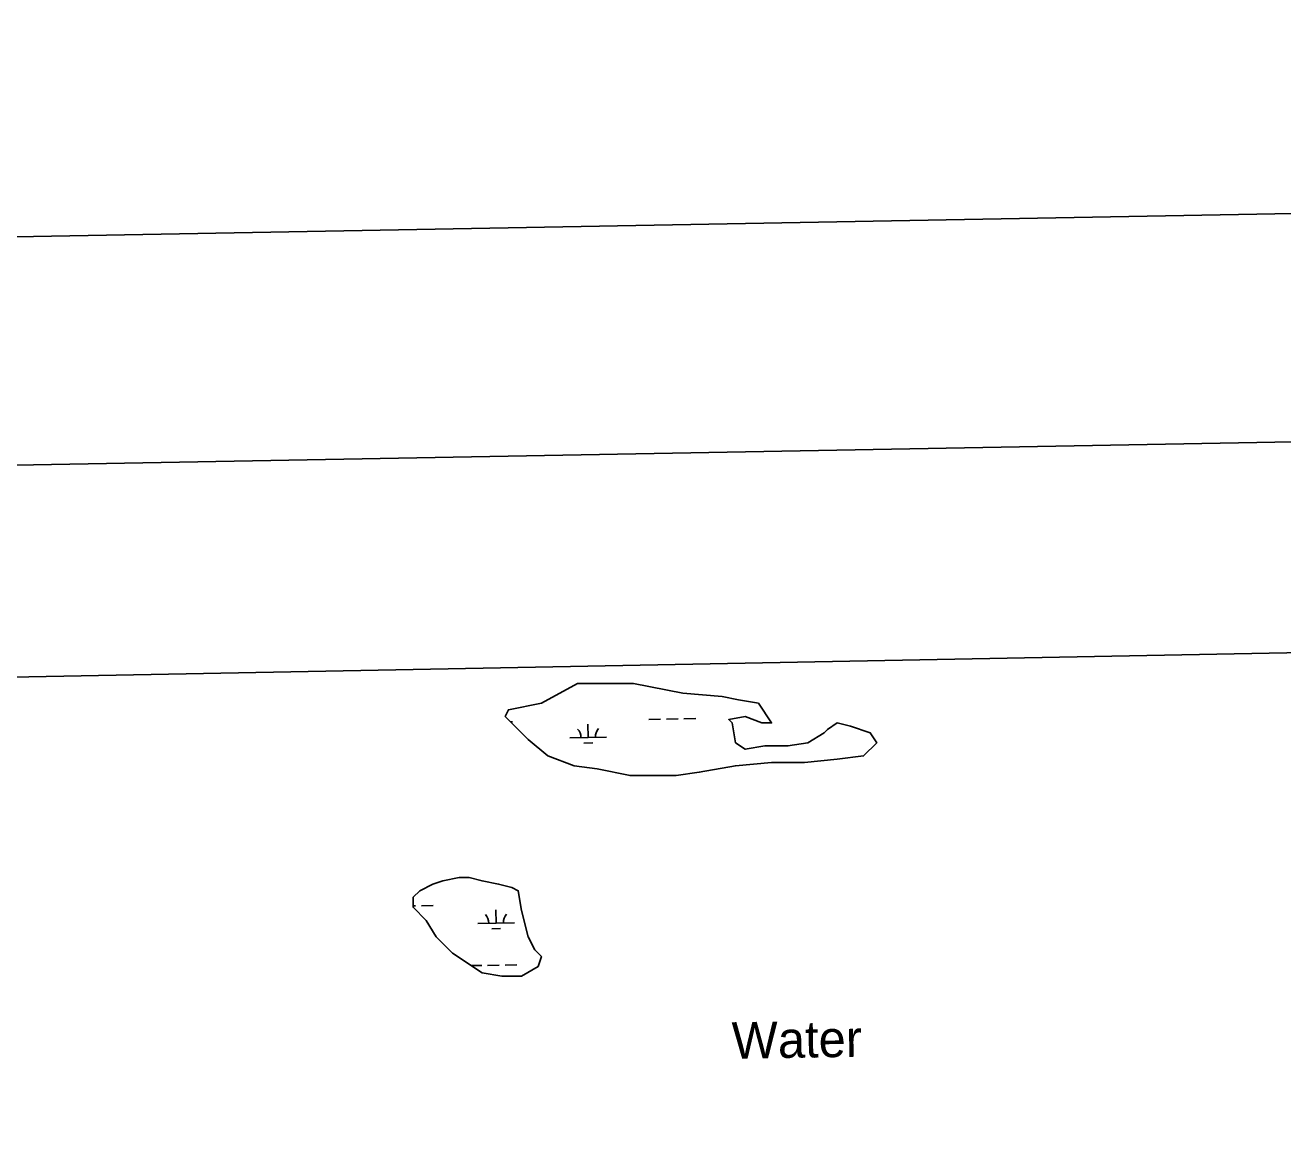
# Model space of a CAD drawing. Extents: x 3957609 to 3995875, y 234277 to 260273.
# Drawn here: x 3963008 to 3966451, y 256682 to 259690 of the extents above; entities that cross this region are included whole.
import ezdxf

# ---------------------------------------------------------------- set-up
doc = ezdxf.new("R2010")
doc.units = 0
for name, color, linetype in [('G-ANNO-NPLT', 7, 'Continuous'), ('V-ANNO-SYMB', 7, 'Continuous'), ('V-GRID-FRAM', 7, 'Continuous'), ('V-RIVR-IDEN', 7, 'Continuous'), ('V-TOPO-SHOR', 7, 'Continuous'), ('V-WETL-SWMP', 7, 'Continuous')]:
    doc.layers.add(name, color=color, linetype=linetype)

msp = doc.modelspace()

# ---------------------------------------------------------------- linework, layer by layer
at = {"layer": 'G-ANNO-NPLT'}
msp.add_lwpolyline([(3958631.604, 234860.578), (3995292.211, 235527.18), (3994852.859, 259689.853), (3958192.252, 259023.251)], close=True, dxfattribs=at)
at = {"layer": 'V-ANNO-SYMB'}
msp.add_lwpolyline([(3961369.919, 235535.518), (3994447.652, 236136.973), (3994031.027, 259049.761), (3960953.294, 258448.306), (3961369.919, 235535.518)], dxfattribs=at)
at = {"layer": 'V-GRID-FRAM'}
for points in [[(3961534.646, 257877.621), (3993438.57, 258485.581), (3993792.928, 240306.336), (3961873.139, 239698.074), (3961534.646, 257877.621)], [(3961534.646, 257877.621), (3993438.57, 258485.581)]]:
    msp.add_lwpolyline(points, dxfattribs=at)
at = {"layer": 'V-TOPO-SHOR'}
for points in [[(3964808.488, 257860.45), (3964916.517, 257851.442), (3964961.528, 257842.433), (3965015.543, 257833.425), (3965051.552, 257779.374), (3965024.545, 257779.374), (3964979.533, 257797.391), (3964934.521, 257788.382), (3964943.524, 257779.374), (3964952.526, 257725.323), (3964979.533, 257707.306), (3965033.547, 257716.315), (3965096.564, 257716.315), (3965150.578, 257725.323), (3965195.59, 257752.349), (3965204.592, 257761.357), (3965231.599, 257779.374), (3965267.608, 257770.366), (3965321.623, 257752.349), (3965339.627, 257725.323), (3965303.618, 257689.289), (3965231.599, 257680.281), (3965141.575, 257671.273), (3965051.552, 257671.273), (3964952.526, 257662.264), (3964853.5, 257644.247), (3964790.484, 257635.239), (3964664.451, 257635.239), (3964574.427, 257653.256), (3964511.411, 257662.264), (3964439.392, 257689.289), (3964385.378, 257734.332), (3964322.361, 257797.391), (3964331.364, 257815.408), (3964421.387, 257833.425), (3964520.413, 257887.475), (3964673.453, 257887.475)], [(3964367.373, 257265.892), (3964385.378, 257193.825), (3964403.383, 257157.791), (3964421.387, 257139.774), (3964412.385, 257112.748), (3964367.373, 257085.723), (3964313.359, 257085.723), (3964259.345, 257094.732), (3964178.324, 257148.782), (3964133.312, 257193.825), (3964106.305, 257238.867), (3964070.296, 257274.901), (3964070.296, 257301.926), (3964088.3, 257319.943), (3964124.31, 257337.96), (3964151.317, 257346.968), (3964196.328, 257355.977), (3964223.336, 257355.977), (3964259.345, 257346.968), (3964304.357, 257337.96), (3964340.366, 257328.951), (3964358.371, 257319.943)]]:
    msp.add_lwpolyline(points, close=True, dxfattribs=at)
at = {"layer": 'V-WETL-SWMP'}
for p, q in [((3964715.878, 257789.175), (3964747.873, 257789.756)), ((3964715.878, 257789.175), (3964747.873, 257789.756)), ((3964715.878, 257789.175), (3964747.873, 257789.756)), ((3964763.87, 257790.047), (3964795.865, 257790.629)), ((3964763.87, 257790.047), (3964795.865, 257790.629)), ((3964763.87, 257790.047), (3964795.865, 257790.629)), ((3964811.862, 257790.92), (3964843.857, 257791.502)), ((3964811.862, 257790.92), (3964843.857, 257791.502)), ((3964811.862, 257790.92), (3964843.857, 257791.502)), ((3964337.448, 257782.294), (3964342.032, 257782.377)), ((3964337.448, 257782.294), (3964342.032, 257782.377)), ((3964337.448, 257782.294), (3964342.032, 257782.377)), ((3964549.686, 257739.715), (3964549.031, 257775.709)), ((3964549.686, 257739.715), (3964549.031, 257775.709)), ((3964549.686, 257739.715), (3964549.031, 257775.709)), ((3965050.956, 257779.374), (3965050.939, 257780.294)), ((3965050.956, 257779.374), (3965050.939, 257780.294)), ((3965050.956, 257779.374), (3965050.939, 257780.294)), ((3964499.694, 257738.806), (3964599.677, 257740.624)), ((3964499.694, 257738.806), (3964599.677, 257740.624)), ((3964499.694, 257738.806), (3964599.677, 257740.624)), ((3964537.968, 257724.068), (3964561.964, 257724.505)), ((3964537.968, 257724.068), (3964561.964, 257724.505)), ((3964537.968, 257724.068), (3964561.964, 257724.505)), ((3964070.296, 257278.177), (3964077.244, 257278.304)), ((3964070.296, 257278.177), (3964077.244, 257278.304)), ((3964070.296, 257278.177), (3964077.244, 257278.304)), ((3964093.241, 257278.595), (3964125.236, 257279.176)), ((3964093.241, 257278.595), (3964125.236, 257279.176)), ((3964093.241, 257278.595), (3964125.236, 257279.176)), ((3964297.446, 257231.557), (3964296.792, 257267.551)), ((3964297.446, 257231.557), (3964296.792, 257267.551)), ((3964297.446, 257231.557), (3964296.792, 257267.551)), ((3964247.455, 257230.648), (3964347.438, 257232.466)), ((3964247.455, 257230.648), (3964347.438, 257232.466)), ((3964247.455, 257230.648), (3964347.438, 257232.466)), ((3964285.729, 257215.911), (3964309.725, 257216.347)), ((3964285.729, 257215.911), (3964309.725, 257216.347)), ((3964285.729, 257215.911), (3964309.725, 257216.347)), ((3964229.166, 257114.865), (3964258.144, 257115.392)), ((3964229.166, 257114.865), (3964258.144, 257115.392)), ((3964229.166, 257114.865), (3964258.144, 257115.392)), ((3964274.141, 257115.683), (3964306.136, 257116.264)), ((3964274.141, 257115.683), (3964306.136, 257116.264)), ((3964274.141, 257115.683), (3964306.136, 257116.264)), ((3964322.133, 257116.555), (3964354.128, 257117.137)), ((3964322.133, 257116.555), (3964354.128, 257117.137)), ((3964322.133, 257116.555), (3964354.128, 257117.137))]:
    msp.add_line(p, q, dxfattribs=at)
for points in [[(3964808.488, 257860.45), (3964916.517, 257851.442), (3964961.528, 257842.433), (3965015.543, 257833.425), (3965051.552, 257779.374), (3965024.545, 257779.374), (3964979.533, 257797.391), (3964934.521, 257788.382), (3964943.524, 257779.374), (3964952.526, 257725.323), (3964979.533, 257707.306), (3965033.547, 257716.315), (3965096.564, 257716.315), (3965150.578, 257725.323), (3965195.59, 257752.349), (3965204.592, 257761.357), (3965231.599, 257779.374), (3965267.608, 257770.366), (3965321.623, 257752.349), (3965339.627, 257725.323), (3965303.618, 257689.289), (3965231.599, 257680.281), (3965141.575, 257671.273), (3965051.552, 257671.273), (3964952.526, 257662.264), (3964853.5, 257644.247), (3964790.484, 257635.239), (3964664.451, 257635.239), (3964574.427, 257653.256), (3964511.411, 257662.264), (3964439.392, 257689.289), (3964385.378, 257734.332), (3964322.361, 257797.391), (3964331.364, 257815.408), (3964421.387, 257833.425), (3964520.413, 257887.475), (3964673.453, 257887.475)], [(3964808.488, 257860.45), (3964916.517, 257851.442), (3964961.528, 257842.433), (3965015.543, 257833.425), (3965051.552, 257779.374), (3965024.545, 257779.374), (3964979.533, 257797.391), (3964934.521, 257788.382), (3964943.524, 257779.374), (3964952.526, 257725.323), (3964979.533, 257707.306), (3965033.547, 257716.315), (3965096.564, 257716.315), (3965150.578, 257725.323), (3965195.59, 257752.349), (3965204.592, 257761.357), (3965231.599, 257779.374), (3965267.608, 257770.366), (3965321.623, 257752.349), (3965339.627, 257725.323), (3965303.618, 257689.289), (3965231.599, 257680.281), (3965141.575, 257671.273), (3965051.552, 257671.273), (3964952.526, 257662.264), (3964853.5, 257644.247), (3964790.484, 257635.239), (3964664.451, 257635.239), (3964574.427, 257653.256), (3964511.411, 257662.264), (3964439.392, 257689.289), (3964385.378, 257734.332), (3964322.361, 257797.391), (3964331.364, 257815.408), (3964421.387, 257833.425), (3964520.413, 257887.475), (3964673.453, 257887.475)], [(3964808.488, 257860.45), (3964916.517, 257851.442), (3964961.528, 257842.433), (3965015.543, 257833.425), (3965051.552, 257779.374), (3965024.545, 257779.374), (3964979.533, 257797.391), (3964934.521, 257788.382), (3964943.524, 257779.374), (3964952.526, 257725.323), (3964979.533, 257707.306), (3965033.547, 257716.315), (3965096.564, 257716.315), (3965150.578, 257725.323), (3965195.59, 257752.349), (3965204.592, 257761.357), (3965231.599, 257779.374), (3965267.608, 257770.366), (3965321.623, 257752.349), (3965339.627, 257725.323), (3965303.618, 257689.289), (3965231.599, 257680.281), (3965141.575, 257671.273), (3965051.552, 257671.273), (3964952.526, 257662.264), (3964853.5, 257644.247), (3964790.484, 257635.239), (3964664.451, 257635.239), (3964574.427, 257653.256), (3964511.411, 257662.264), (3964439.392, 257689.289), (3964385.378, 257734.332), (3964322.361, 257797.391), (3964331.364, 257815.408), (3964421.387, 257833.425), (3964520.413, 257887.475), (3964673.453, 257887.475)], [(3964367.373, 257265.892), (3964385.378, 257193.825), (3964403.383, 257157.791), (3964421.387, 257139.774), (3964412.385, 257112.748), (3964367.373, 257085.723), (3964313.359, 257085.723), (3964259.345, 257094.732), (3964178.324, 257148.782), (3964133.312, 257193.825), (3964106.305, 257238.867), (3964070.296, 257274.901), (3964070.296, 257301.926), (3964088.3, 257319.943), (3964124.31, 257337.96), (3964151.317, 257346.968), (3964196.328, 257355.977), (3964223.336, 257355.977), (3964259.345, 257346.968), (3964304.357, 257337.96), (3964340.366, 257328.951), (3964358.371, 257319.943)], [(3964367.373, 257265.892), (3964385.378, 257193.825), (3964403.383, 257157.791), (3964421.387, 257139.774), (3964412.385, 257112.748), (3964367.373, 257085.723), (3964313.359, 257085.723), (3964259.345, 257094.732), (3964178.324, 257148.782), (3964133.312, 257193.825), (3964106.305, 257238.867), (3964070.296, 257274.901), (3964070.296, 257301.926), (3964088.3, 257319.943), (3964124.31, 257337.96), (3964151.317, 257346.968), (3964196.328, 257355.977), (3964223.336, 257355.977), (3964259.345, 257346.968), (3964304.357, 257337.96), (3964340.366, 257328.951), (3964358.371, 257319.943)], [(3964367.373, 257265.892), (3964385.378, 257193.825), (3964403.383, 257157.791), (3964421.387, 257139.774), (3964412.385, 257112.748), (3964367.373, 257085.723), (3964313.359, 257085.723), (3964259.345, 257094.732), (3964178.324, 257148.782), (3964133.312, 257193.825), (3964106.305, 257238.867), (3964070.296, 257274.901), (3964070.296, 257301.926), (3964088.3, 257319.943), (3964124.31, 257337.96), (3964151.317, 257346.968), (3964196.328, 257355.977), (3964223.336, 257355.977), (3964259.345, 257346.968), (3964304.357, 257337.96), (3964340.366, 257328.951), (3964358.371, 257319.943)]]:
    msp.add_lwpolyline(points, close=True, dxfattribs=at)
for centre, start, end in [((3964494.443, 257739.186), 0.269879, 41.813537), ((3964494.443, 257739.186), 0.269879, 41.813537), ((3964494.443, 257739.186), 0.269879, 41.813537), ((3964604.911, 257741.194), 140.269876, 181.813534), ((3964604.911, 257741.194), 140.269876, 181.813534), ((3964604.911, 257741.194), 140.269876, 181.813534), ((3964242.204, 257231.028), 0.269879, 41.813537), ((3964242.204, 257231.028), 0.269879, 41.813537), ((3964242.204, 257231.028), 0.269879, 41.813537), ((3964352.672, 257233.036), 140.269876, 181.813534), ((3964352.672, 257233.036), 140.269876, 181.813534), ((3964352.672, 257233.036), 140.269876, 181.813534)]:
    msp.add_arc(centre, 35.246, start, end, dxfattribs=at)

# ---------------------------------------------------------------- texts
at = {"layer": 'V-RIVR-IDEN'}
msp.add_text('Water', height=99.9998, rotation=0.902342, dxfattribs=at).set_placement((3964943.415, 256859.951))

doc.saveas('drawing.dxf')
